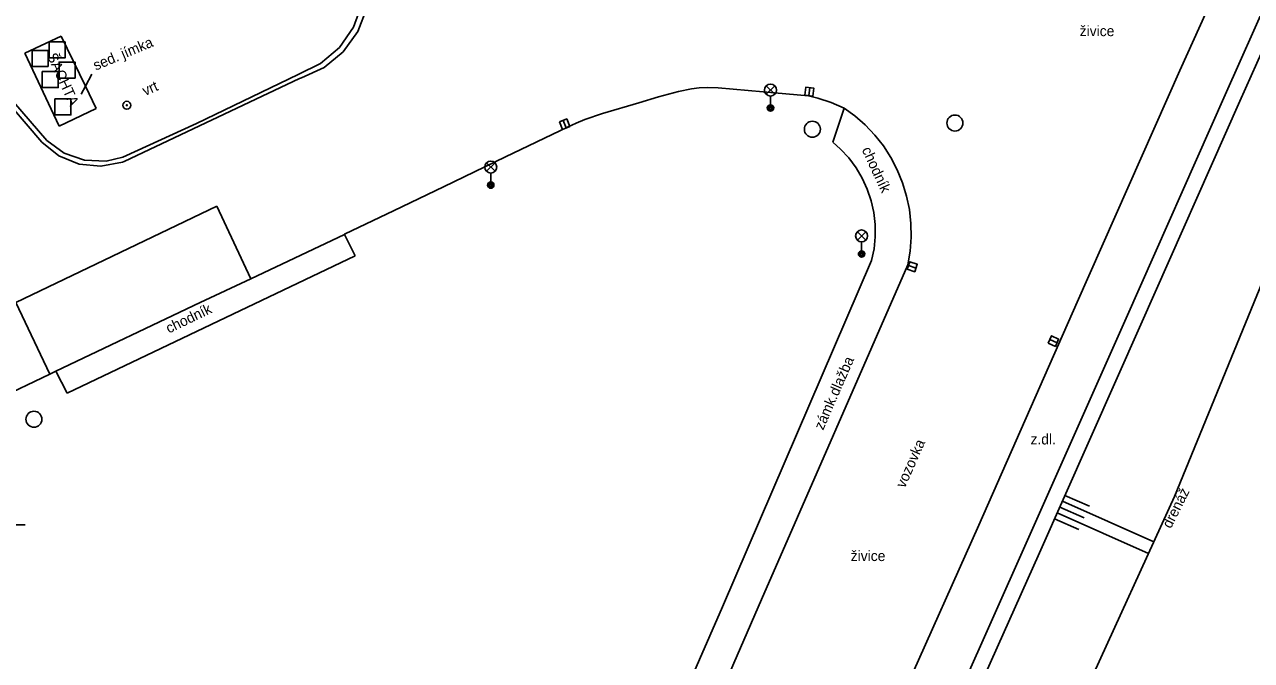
# Model space of a CAD drawing. Extents: x -538441 to -536770, y -1181008 to -1179809.
# Drawn here: x -538088.6 to -538011.8, y -1180273.6 to -1180233.8 of the extents above; entities that cross this region are included whole.
import ezdxf

# ---------------------------------------------------------------- set-up
doc = ezdxf.new("R2010")
doc.units = 0
for name, color, linetype in [('Vrstva 10', 7, 'Continuous'), ('Vrstva 11', 7, 'Continuous'), ('Vrstva 14', 7, 'Continuous'), ('Vrstva 15', 7, 'Continuous'), ('Vrstva 25', 7, 'Continuous'), ('Vrstva 26', 7, 'Continuous'), ('Vrstva 27', 7, 'Continuous'), ('Vrstva 33', 7, 'Continuous'), ('Vrstva 35', 7, 'Continuous'), ('Vrstva 40', 7, 'Continuous')]:
    doc.layers.add(name, color=color, linetype=linetype)

msp = doc.modelspace()

# ---------------------------------------------------------------- linework, layer by layer
at = {"layer": 'Vrstva 10'}
for p, q in [((-538016.266, -1180236.713), (-538013.293, -1180230.089)), ((-538086.25, -1180234.56), (-538088.53, -1180235.63)), ((-538088.53, -1180235.63), (-538086.392, -1180240.184)), ((-538087.46, -1180241.18), (-538091.95, -1180235.96)), ((-538082.31, -1180242.39), (-538071.34, -1180237.2)), ((-538022.684, -1180251.2), (-538016.266, -1180236.713)), ((-538084.06, -1180239.09), (-538086.392, -1180240.184)), ((-538054.57, -1180240.241), (-538058.455, -1180242.114)), ((-538065.43, -1180245.469), (-538068.522, -1180246.949)), ((-538068.532, -1180246.954), (-538074.389, -1180249.725)), ((-538068.522, -1180246.949), (-538068.532, -1180246.954)), ((-538042.442, -1180269.799), (-538033.283, -1180248.856)), ((-538074.389, -1180249.725), (-538077.554, -1180251.223)), ((-538077.554, -1180251.223), (-538086.583, -1180255.502)), ((-538028.846, -1180265.133), (-538022.684, -1180251.2)), ((-538086.583, -1180255.502), (-538086.973, -1180255.689)), ((-538086.973, -1180255.689), (-538094.269, -1180259.179)), ((-538036.324, -1180281.869), (-538028.846, -1180265.133)), ((-538048.637, -1180284.029), (-538042.442, -1180269.799))]:
    msp.add_line(p, q, dxfattribs=at)
for points in [[(-538066.96, -1180231.27), (-538067.135, -1180232.816), (-538067.698, -1180234.267), (-538068.61, -1180235.528), (-538069.812, -1180236.515), (-538071.226, -1180237.166), (-538071.34, -1180237.2)], [(-538086.25, -1180234.56), (-538084.737, -1180237.69), (-538084.06, -1180239.09)], [(-538084.33, -1180236.939), (-538084.737, -1180237.69), (-538085.001, -1180238.179)], [(-538039.492, -1180238.294), (-538042.328, -1180238.041), (-538045.163, -1180237.788), (-538045.79, -1180237.766), (-538046.337, -1180237.796), (-538046.814, -1180237.855), (-538047.645, -1180238.017), (-538048.887, -1180238.352)], [(-538048.887, -1180238.352), (-538050.124, -1180238.722), (-538052.39, -1180239.394), (-538053.494, -1180239.78), (-538054.036, -1180239.999), (-538054.57, -1180240.241)], [(-538037.266, -1180239.053), (-538038.08, -1180238.705), (-538038.922, -1180238.433), (-538039.492, -1180238.294)], [(-538035.949, -1180240.113), (-538036.6, -1180239.54), (-538037.266, -1180239.053)], [(-538033.283, -1180248.856), (-538033.14, -1180248), (-538033.077, -1180247.135), (-538033.094, -1180246.268), (-538033.191, -1180245.406), (-538033.366, -1180244.557), (-538033.619, -1180243.727), (-538033.947, -1180242.924), (-538034.348, -1180242.155), (-538034.818, -1180241.426), (-538035.353, -1180240.743), (-538035.949, -1180240.113)], [(-538087.46, -1180241.18), (-538086.397, -1180242.042), (-538085.13, -1180242.562), (-538083.768, -1180242.696), (-538082.425, -1180242.432), (-538082.31, -1180242.39)], [(-538058.455, -1180242.114), (-538062.34, -1180243.986), (-538065.43, -1180245.469)]]:
    msp.add_lwpolyline(points, dxfattribs=at)
at = {"layer": 'Vrstva 11'}
for p, q in [((-538013.435, -1180238.226), (-538010.526, -1180231.697)), ((-538087.156, -1180241.081), (-538091.701, -1180235.842)), ((-538077.8, -1180240.01), (-538071.44, -1180236.95)), ((-538019.628, -1180252.189), (-538013.435, -1180238.226)), ((-538037.974, -1180241.193), (-538037.266, -1180239.053)), ((-538077.8, -1180240.01), (-538082.399, -1180242.133)), ((-538076.51, -1180245.19), (-538089.09, -1180251.22)), ((-538074.389, -1180249.725), (-538076.51, -1180245.19)), ((-538067.862, -1180248.297), (-538068.532, -1180246.954)), ((-538085.89, -1180256.886), (-538067.862, -1180248.297)), ((-538044.881, -1180270.253), (-538035.557, -1180248.599)), ((-538089.09, -1180251.22), (-538086.973, -1180255.689)), ((-538025.964, -1180266.464), (-538019.628, -1180252.189)), ((-538086.583, -1180255.502), (-538085.89, -1180256.886)), ((-538033.312, -1180282.89), (-538025.964, -1180266.464)), ((-538048.885, -1180279.416), (-538044.881, -1180270.253))]:
    msp.add_line(p, q, dxfattribs=at)
for points in [[(-538071.44, -1180236.95), (-538070.039, -1180236.273), (-538068.855, -1180235.263), (-538067.967, -1180233.986), (-538067.432, -1180232.524), (-538067.286, -1180230.975), (-538067.537, -1180229.44)], [(-538087.156, -1180241.081), (-538086.069, -1180241.878), (-538084.798, -1180242.322), (-538083.452, -1180242.376), (-538082.399, -1180242.133)], [(-538035.557, -1180248.599), (-538035.404, -1180247.856), (-538035.33, -1180247.101), (-538035.336, -1180246.342), (-538035.421, -1180245.588), (-538035.586, -1180244.847), (-538035.827, -1180244.127), (-538036.143, -1180243.437), (-538036.529, -1180242.784), (-538036.983, -1180242.176), (-538037.497, -1180241.618), (-538037.974, -1180241.193)]]:
    msp.add_lwpolyline(points, dxfattribs=at)
at = {"layer": 'Vrstva 14'}
for p, q in [((-538012.521, -1180238.631), (-538009.691, -1180232.279)), ((-538018.714, -1180252.594), (-538012.521, -1180238.631)), ((-538008.959, -1180244.65), (-538016.594, -1180263.358)), ((-538025.05, -1180266.87), (-538018.714, -1180252.594)), ((-538016.594, -1180263.358), (-538024.739, -1180281.13)), ((-538032.353, -1180283.196), (-538025.05, -1180266.87))]:
    msp.add_line(p, q, dxfattribs=at)
at = {"layer": 'Vrstva 15'}
for p, q in [((-538023.457, -1180263.281), (-538021.93, -1180263.959)), ((-538023.782, -1180264.012), (-538022.255, -1180264.69)), ((-538023.619, -1180263.647), (-538017.892, -1180266.19)), ((-538024.106, -1180264.743), (-538022.579, -1180265.421)), ((-538023.944, -1180264.378), (-538018.225, -1180266.917))]:
    msp.add_line(p, q, dxfattribs=at)
at = {"layer": 'Vrstva 25'}
for radius in [0.25, 0.0303]:
    msp.add_circle((-538082.15, -1180238.88), radius, dxfattribs=at)
at = {"layer": 'Vrstva 26'}
for points in [[(-538087.01, -1180235.92), (-538086.01, -1180235.92), (-538086.01, -1180234.92), (-538087.01, -1180234.92)], [(-538088.08, -1180236.45), (-538087.08, -1180236.45), (-538087.08, -1180235.45), (-538088.08, -1180235.45)], [(-538086.39, -1180237.18), (-538085.39, -1180237.18), (-538085.39, -1180236.18), (-538086.39, -1180236.18)], [(-538087.44, -1180237.77), (-538086.44, -1180237.77), (-538086.44, -1180236.77), (-538087.44, -1180236.77)], [(-538086.65, -1180239.48), (-538085.65, -1180239.48), (-538085.65, -1180238.48), (-538086.65, -1180238.48)]]:
    msp.add_lwpolyline(points, close=True, dxfattribs=at)
at = {"layer": 'Vrstva 27'}
for p, q in [((-538039.487, -1180238.277), (-538039.413, -1180237.783)), ((-538054.856, -1180239.831), (-538054.668, -1180240.293)), ((-538033.247, -1180248.9), (-538032.773, -1180249.06)), ((-538024.41, -1180253.528), (-538023.952, -1180253.73))]:
    msp.add_line(p, q, dxfattribs=at)
for points in [[(-538039.24, -1180238.314), (-538039.166, -1180237.82), (-538039.66, -1180237.746), (-538039.734, -1180238.24)], [(-538055.088, -1180239.925), (-538054.899, -1180240.388), (-538054.436, -1180240.199), (-538054.625, -1180239.736)], [(-538033.327, -1180249.137), (-538032.853, -1180249.297), (-538032.693, -1180248.823), (-538033.167, -1180248.663)], [(-538024.511, -1180253.756), (-538024.054, -1180253.959), (-538023.851, -1180253.502), (-538024.308, -1180253.299)]]:
    msp.add_lwpolyline(points, close=True, dxfattribs=at)
for centre in [(-538030.34, -1180239.99), (-538039.261, -1180240.38), (-538087.96, -1180258.52)]:
    msp.add_circle(centre, 0.5, dxfattribs=at)
at = {"layer": 'Vrstva 33'}
for p, q in [((-538042.145, -1180238.19), (-538041.615, -1180237.66)), ((-538042.145, -1180237.66), (-538041.615, -1180238.19)), ((-538041.88, -1180238.3), (-538041.88, -1180239.05)), ((-538059.645, -1180243.01), (-538059.115, -1180242.48)), ((-538059.645, -1180242.48), (-538059.115, -1180243.01)), ((-538059.38, -1180243.12), (-538059.38, -1180243.87)), ((-538036.445, -1180247.32), (-538035.915, -1180246.79)), ((-538036.445, -1180246.79), (-538035.915, -1180247.32)), ((-538036.18, -1180247.43), (-538036.18, -1180248.18))]:
    msp.add_line(p, q, dxfattribs=at)
for centre, radius in [((-538041.88, -1180237.925), 0.375), ((-538041.88, -1180239.05), 0.2), ((-538041.88, -1180239.05), 0.145), ((-538041.88, -1180239.05), 0.0876), ((-538059.38, -1180242.745), 0.375), ((-538059.38, -1180243.87), 0.2), ((-538059.38, -1180243.87), 0.145), ((-538059.38, -1180243.87), 0.0876), ((-538036.18, -1180247.055), 0.375), ((-538036.18, -1180248.18), 0.2), ((-538036.18, -1180248.18), 0.145), ((-538036.18, -1180248.18), 0.0876)]:
    msp.add_circle(centre, radius, dxfattribs=at)
at = {"layer": 'Vrstva 35'}
msp.add_line((-538089.505, -1180265.12), (-538088.505, -1180265.12), dxfattribs=at)

# ---------------------------------------------------------------- texts
at = {"layer": 'Vrstva 40'}
for s, p in [('živice', (-538022.537, -1180234.557)), ('z.dl.', (-538025.616, -1180260.093)), ('živice', (-538036.862, -1180267.387))]:
    msp.add_text(s, height=0.65, dxfattribs=at).set_placement(p)
for s, rotation, p in [('sed. jímka', 22.88572, (-538084.091, -1180236.716)), ('ŠACHTA', 294.35558, (-538087.159, -1180235.784)), ('vrt', 23.67597, (-538081.011, -1180238.305)), ('chodník', 294.74033, (-538036.183, -1180241.655)), ('chodník', 25.84535, (-538079.516, -1180253.164)), ('zámk.dlažba', 66.3788, (-538038.588, -1180259.239)), ('vozovka', 66.10556, (-538033.48, -1180262.867)), ('drenáž', 63.46155, (-538016.832, -1180265.395))]:
    msp.add_text(s, height=0.65, rotation=rotation, dxfattribs=at).set_placement(p)

doc.saveas('drawing.dxf')
